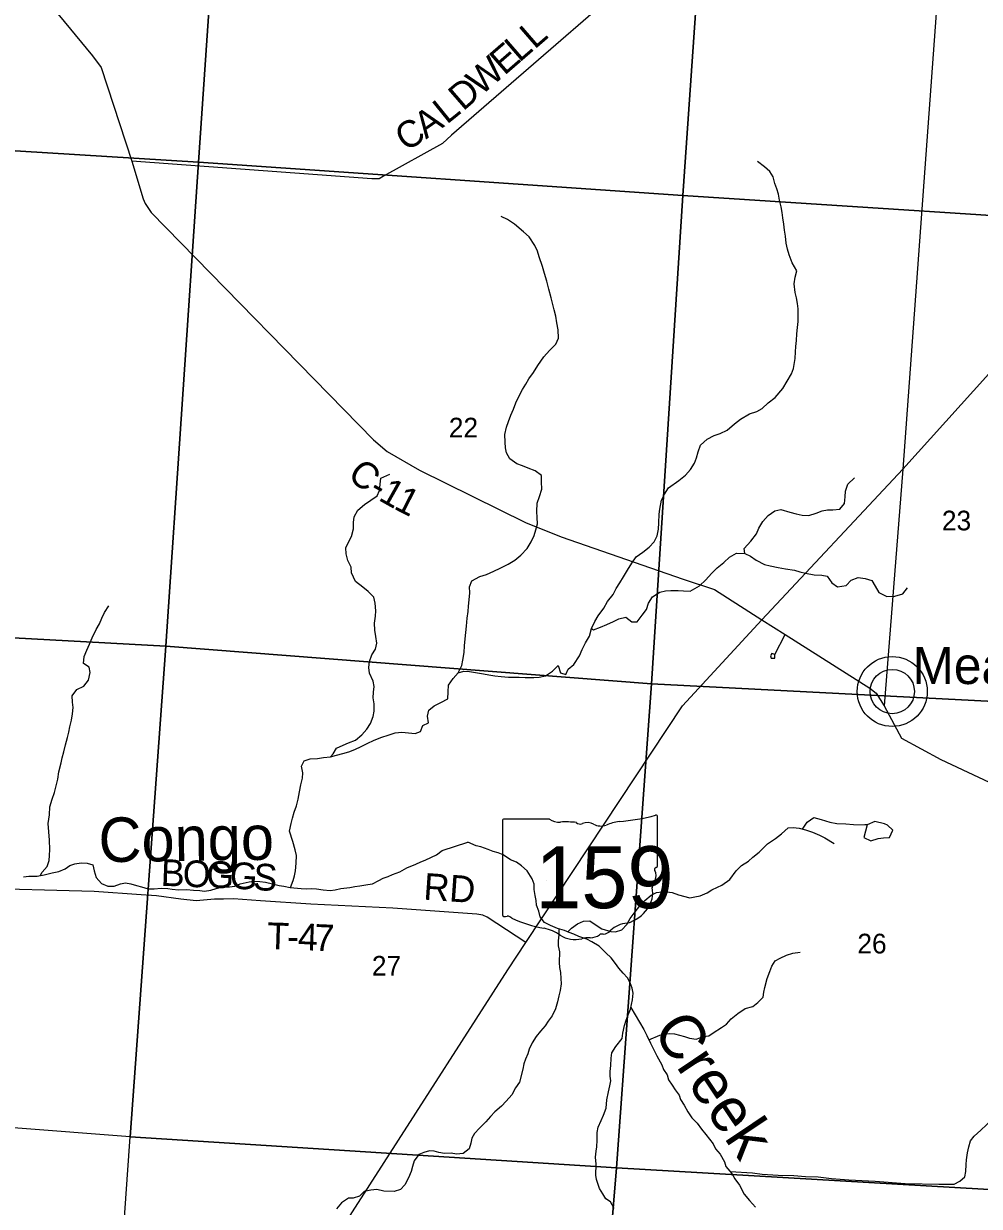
# Model space of a CAD drawing. Extents: x 1643459 to 2064572, y 425441 to 780708.
# Drawn here: x 1852387 to 1863118, y 542483 to 555768 of the extents above; entities that cross this region are included whole.
import ezdxf

# ---------------------------------------------------------------- set-up
doc = ezdxf.new("R2010")
doc.units = 0
for name, color, linetype in [('GE_P_Alignment_100_Curve_Data', 7, 'Continuous'), ('GM_X_Adjacent_County', 7, 'Continuous'), ('GM_X_County', 7, 'Continuous'), ('GM_X_Interchange_Ramps', 7, 'Continuous'), ('GM_X_Major_River', 7, 'Continuous'), ('GM_X_Major_River_Text', 7, 'Continuous'), ('GM_X_Minor_Lake', 7, 'Continuous'), ('GM_X_Rail_Line', 7, 'Continuous'), ('GM_X_Section_Text', 7, 'Continuous'), ('GM_X_State_Route', 7, 'Continuous'), ('GM_X_Township_ROW', 7, 'Continuous'), ('GM_X_Township_Subdivision_Text', 7, 'Continuous'), ('GM_X_US_Route', 7, 'Continuous'), ('PM_P_Cells', 7, 'Continuous'), ('RD_X_Text', 7, 'Continuous'), ('ST_Details', 7, 'Continuous')]:
    doc.layers.add(name, color=color, linetype=linetype)

msp = doc.modelspace()

# ---------------------------------------------------------------- linework, layer by layer
at = {"layer": 'GE_P_Alignment_100_Curve_Data'}
for radius in [393, 249]:
    msp.add_circle((1862140, 548266), radius, dxfattribs=at)
at = {"layer": 'GM_X_County'}
msp.add_lwpolyline([(1860822, 548681), (1860786, 548692), (1860773, 548668), (1860782, 548642), (1860820, 548640), (1860823, 548681), (1860938, 548905)], dxfattribs=at)
at = {"layer": 'GM_X_Major_River_Text'}
for points in [[(1862916, 559716), (1862715, 557017), (1862259, 550763)], [(1859898, 556864), (1859897, 556864), (1857192, 554514), (1857090, 554421), (1856429, 554054), (1856379, 554026), (1856295, 554025), (1853603, 554223)], [(1862259, 550763), (1862259, 550763), (1862050, 548106)], [(1858025, 545447), (1857592, 545730), (1857542, 545752), (1857477, 545766), (1856531, 545831), (1855610, 545879), (1855048, 545914), (1854745, 545936), (1854631, 545934), (1854529, 545933), (1854326, 545916), (1854152, 545935), (1853877, 545972), (1853705, 545981), (1853179, 546018), (1851781, 546057), (1851715, 546069), (1851683, 546093), (1851646, 546127), (1851410, 546135), (1848838, 546297)]]:
    msp.add_lwpolyline(points, dxfattribs=at)
at = {"layer": 'GM_X_Minor_Lake'}
for points in [[(1846452, 560096), (1849195, 559926), (1849444, 559910), (1853159, 555407), (1853258, 555276), (1853603, 554223), (1853728, 553801), (1853750, 553748), (1853819, 553648), (1856316, 551094), (1856467, 550961), (1856830, 550751), (1858023, 550164), (1858422, 550003), (1859792, 549529), (1860143, 549412), (1860677, 549070)], [(1860677, 549070), (1860677, 549070), (1860938, 548905), (1861887, 548303), (1861961, 548249), (1862050, 548106), (1862245, 547741), (1862687, 547503), (1864681, 546568), (1865987, 545911), (1866232, 545790), (1866317, 545732), (1866543, 545497)]]:
    msp.add_lwpolyline(points, dxfattribs=at)
at = {"layer": 'GM_X_Rail_Line'}
msp.add_line((1862140, 548266), (1862140, 548266), dxfattribs=at)
at = {"layer": 'GM_X_State_Route'}
for points in [[(1849223, 559965), (1854721, 559628), (1854349, 554212), (1848897, 554550)], [(1854721, 559628), (1860164, 559226), (1859790, 553839), (1854349, 554212)], [(1860164, 559226), (1865614, 558892), (1865211, 553484), (1859790, 553839)], [(1848897, 554550), (1854349, 554212), (1853983, 548777), (1848566, 549071)], [(1854349, 554212), (1859790, 553839), (1859437, 548353), (1853983, 548777)], [(1859790, 553839), (1865211, 553484), (1864802, 548077), (1859437, 548353)], [(1853983, 548777), (1853583, 543265), (1848193, 543679), (1848566, 549071)], [(1859437, 548353), (1859042, 542917), (1853583, 543265), (1853983, 548777)], [(1859437, 548353), (1864802, 548077), (1864390, 542605), (1859042, 542917)], [(1853583, 543265), (1859042, 542917), (1858602, 537565), (1858480, 537574), (1853210, 537937)], [(1859042, 542917), (1864390, 542605), (1863986, 537192), (1858602, 537565)]]:
    msp.add_lwpolyline(points, close=True, dxfattribs=at)
at = {"layer": 'GM_X_Township_Subdivision_Text'}
for points in [[(1861860, 546769), (1861819, 546627), (1861901, 546590), (1861983, 546614), (1862041, 546624), (1862109, 546627), (1862146, 546707), (1862086, 546766), (1862053, 546779)], [(1862053, 546779), (1861944, 546805), (1861860, 546769)]]:
    msp.add_lwpolyline(points, dxfattribs=at)
at = {"layer": 'GM_X_US_Route'}
for points in [[(1857267, 548475), (1857331, 548496), (1857393, 548490), (1857483, 548477), (1857549, 548465), (1857609, 548454), (1857677, 548442), (1857749, 548435), (1857831, 548429), (1857891, 548428), (1857951, 548426), (1858019, 548422), (1858115, 548423), (1858175, 548427), (1858245, 548442), (1858325, 548496), (1858390, 548558), (1858415, 548477), (1858475, 548457), (1858501, 548517), (1858564, 548569), (1858630, 548668), (1858657, 548739), (1858697, 548813), (1858740, 548889), (1858764, 548973), (1858799, 549053), (1858837, 549117), (1858900, 549203), (1858944, 549277), (1859005, 549354), (1859041, 549424), (1859081, 549488), (1859122, 549556), (1859168, 549630), (1859217, 549708), (1859263, 549778), (1859340, 549832), (1859412, 549888), (1859466, 549948), (1859499, 550016), (1859515, 550090), (1859520, 550162), (1859522, 550258), (1859531, 550316), (1859549, 550417), (1859584, 550483), (1859626, 550553), (1859743, 550636), (1859817, 550698), (1859876, 550760), (1859918, 550832), (1859942, 550892), (1859961, 550960), (1859985, 551034), (1860062, 551100), (1860142, 551143), (1860208, 551165), (1860286, 551203), (1860367, 551274), (1860437, 551326), (1860538, 551384), (1860618, 551413), (1860680, 551445), (1860748, 551507), (1860825, 551568), (1860912, 551670), (1861009, 551834), (1861031, 551896), (1861048, 552005), (1861054, 552083), (1861058, 552141), (1861063, 552209), (1861069, 552283), (1861076, 552356), (1861082, 552424), (1861085, 552496), (1861083, 552566), (1861075, 552624), (1861066, 552689), (1861050, 552749), (1861037, 552844), (1861051, 552920), (1861070, 552990), (1861016, 553082), (1860981, 553173), (1860963, 553235), (1860949, 553302), (1860942, 553382), (1860930, 553450), (1860921, 553515), (1860911, 553585), (1860902, 553645), (1860892, 553709), (1860874, 553786), (1860863, 553852), (1860843, 553912), (1860823, 553971), (1860804, 554047), (1860766, 554108), (1860705, 554160)], [(1860705, 554160), (1860625, 554219)], [(1858375, 552409), (1858361, 552481), (1858342, 552554), (1858330, 552612), (1858311, 552688), (1858285, 552787), (1858260, 552875), (1858236, 552960), (1858213, 553042), (1858175, 553149), (1858156, 553211), (1858126, 553276), (1858063, 553372), (1857999, 553431), (1857899, 553514), (1857818, 553569), (1857748, 553601)], [(1855409, 546581), (1855371, 546697), (1855389, 546783), (1855404, 546845), (1855424, 546909), (1855451, 546983), (1855469, 547055), (1855486, 547139), (1855500, 547216), (1855519, 547292), (1855523, 547354), (1855507, 547426), (1855536, 547488), (1855604, 547508), (1855686, 547515), (1855754, 547525), (1855832, 547532), (1855898, 547552), (1855972, 547568), (1856037, 547589), (1856105, 547613), (1856177, 547649), (1856243, 547682), (1856324, 547720), (1856410, 547752), (1856480, 547775), (1856558, 547803), (1856634, 547808), (1856710, 547800), (1856782, 547793), (1856842, 547817), (1856869, 547883), (1856933, 547915), (1856923, 547989), (1856936, 548057), (1856998, 548107), (1857070, 548141), (1857149, 548184), (1857153, 548263), (1857158, 548339), (1857210, 548411), (1857267, 548475), (1857307, 548559), (1857319, 548619), (1857332, 548705), (1857338, 548779), (1857345, 548857), (1857353, 548928), (1857360, 549000), (1857368, 549090), (1857377, 549166), (1857381, 549226), (1857388, 549297), (1857396, 549375), (1857392, 549443), (1857421, 549511), (1857509, 549557), (1857583, 549580), (1857668, 549616), (1857736, 549650), (1857826, 549697), (1857901, 549743), (1857969, 549797), (1858039, 549872), (1858086, 549948), (1858120, 550020), (1858139, 550081), (1858157, 550149), (1858154, 550219), (1858150, 550287), (1858153, 550381), (1858179, 550458), (1858204, 550540), (1858202, 550622), (1858202, 550692), (1858129, 550745), (1858053, 550775), (1857989, 550800), (1857923, 550824), (1857847, 550879), (1857810, 550946), (1857798, 551004), (1857793, 551068), (1857789, 551152), (1857808, 551237), (1857830, 551299), (1857858, 551371), (1857887, 551437), (1857915, 551509), (1857950, 551589), (1857990, 551657), (1858025, 551717), (1858061, 551779), (1858113, 551851), (1858160, 551929), (1858227, 552027), (1858293, 552096), (1858363, 552166), (1858392, 552234), (1858390, 552329), (1858375, 552409)], [(1855832, 547532), (1855864, 547566), (1855899, 547630), (1855973, 547664), (1856035, 547690), (1856113, 547721), (1856186, 547779), (1856240, 547843), (1856281, 547907), (1856313, 547987), (1856324, 548047), (1856322, 548129), (1856312, 548196), (1856317, 548260), (1856323, 548324), (1856312, 548382), (1856272, 548473), (1856262, 548537), (1856271, 548605), (1856297, 548677), (1856338, 548741), (1856354, 548810), (1856341, 548884), (1856329, 548954), (1856326, 549033), (1856338, 549113), (1856340, 549173), (1856335, 549257), (1856319, 549324), (1856256, 549390), (1856194, 549439), (1856114, 549501), (1856069, 549598), (1856063, 549664), (1856026, 549739), (1856008, 549811), (1856005, 549879), (1856033, 549942), (1856067, 550008), (1856092, 550092), (1856090, 550166), (1856099, 550230), (1856141, 550304), (1856214, 550368), (1856286, 550416), (1856358, 550465), (1856383, 550525), (1856399, 550662), (1856500, 550709)], [(1860486, 549817), (1860478, 549871), (1860553, 549953), (1860616, 550038), (1860642, 550099), (1860688, 550177), (1860747, 550242), (1860821, 550296), (1860889, 550312), (1860989, 550281), (1861061, 550262), (1861129, 550248), (1861205, 550243), (1861285, 550269), (1861353, 550295), (1861414, 550306), (1861474, 550306), (1861550, 550313), (1861604, 550377), (1861612, 550454), (1861615, 550518), (1861641, 550596), (1861716, 550668)], [(1858764, 548973), (1858786, 548958), (1858864, 548990), (1858935, 549018), (1859011, 549051), (1859069, 549081), (1859147, 549101), (1859217, 549048), (1859277, 549050), (1859331, 549122), (1859380, 549189), (1859404, 549260), (1859449, 549330), (1859531, 549381), (1859593, 549397), (1859653, 549402), (1859735, 549400), (1859797, 549398), (1859871, 549393), (1859974, 549453), (1860046, 549522), (1860109, 549590), (1860173, 549654), (1860247, 549714), (1860312, 549774), (1860392, 549819), (1860486, 549817), (1860550, 549786), (1860612, 549740), (1860705, 549693), (1860769, 549676), (1860857, 549660), (1860941, 549645), (1861041, 549628), (1861103, 549612), (1861167, 549595), (1861263, 549577), (1861349, 549572), (1861409, 549560), (1861461, 549487), (1861526, 549441), (1861622, 549456), (1861677, 549516), (1861757, 549545), (1861835, 549537), (1861909, 549514), (1861949, 549450), (1861990, 549377), (1862078, 549333), (1862170, 549338), (1862258, 549364), (1862311, 549430)], [(1852678, 546595), (1852662, 546784), (1852678, 546880), (1852681, 546971), (1852706, 547055), (1852734, 547133), (1852753, 547205), (1852771, 547283), (1852784, 547363), (1852808, 547464), (1852821, 547522), (1852837, 547588), (1852858, 547666), (1852880, 547750), (1852893, 547808), (1852907, 547870), (1852925, 547945), (1852936, 548015), (1852942, 548085), (1852935, 548145), (1852931, 548219), (1852984, 548287), (1853062, 548327), (1853114, 548395), (1853135, 548481), (1853123, 548541), (1853061, 548580), (1853068, 548658), (1853098, 548732), (1853127, 548798), (1853155, 548868), (1853202, 548962), (1853238, 549026), (1853265, 549090), (1853295, 549154), (1853343, 549230)], [(1861133, 546719), (1861186, 546798), (1861260, 546849), (1861342, 546827), (1861438, 546798), (1861518, 546785), (1861620, 546779), (1861704, 546774), (1861860, 546769), (1861831, 546769)], [(1860740, 546555), (1860829, 546615), (1860895, 546669), (1860970, 546735), (1861028, 546740), (1861096, 546732), (1861164, 546711), (1861245, 546685), (1861323, 546652), (1861383, 546624), (1861489, 546559)], [(1852385, 546186), (1852446, 546191), (1852540, 546190), (1852618, 546207), (1852707, 546228), (1852781, 546245), (1852854, 546276), (1852904, 546312), (1852963, 546331), (1853033, 546341), (1853101, 546338), (1853163, 546319), (1853180, 546252), (1853203, 546176), (1853263, 546109), (1853331, 546080), (1853403, 546079), (1853475, 546106), (1853532, 546117), (1853590, 546105), (1853654, 546086), (1853710, 546073), (1853784, 546050), (1853854, 546049), (1853932, 546058), (1854006, 546053), (1854056, 546045), (1854126, 546038), (1854217, 546041), (1854293, 546034), (1854367, 546029), (1854417, 546022), (1854487, 546033), (1854550, 546055), (1854624, 546072), (1854698, 546073), (1854759, 546080), (1854817, 546105), (1854920, 546130), (1854970, 546136), (1855038, 546133), (1855104, 546124), (1855180, 546105), (1855256, 546088), (1855310, 546081), (1855380, 546064), (1855502, 546053), (1855566, 546048), (1855623, 546053), (1855675, 546051), (1855749, 546040), (1855829, 546031), (1855885, 546038), (1855950, 546053), (1856048, 546064), (1856104, 546075), (1856162, 546085), (1856253, 546098), (1856305, 546107), (1856374, 546144), (1856424, 546170), (1856479, 546189), (1856529, 546209), (1856610, 546242), (1856690, 546287), (1856791, 546328), (1856846, 546351), (1856896, 546373), (1856967, 546404), (1857021, 546432), (1857086, 546479), (1857375, 546572)], [(1852572, 546197), (1852596, 546237), (1852651, 546301), (1852674, 546367), (1852679, 546423), (1852680, 546492), (1852678, 546595)], [(1855383, 546064), (1855415, 546144), (1855428, 546194), (1855438, 546250), (1855448, 546339), (1855449, 546425), (1855437, 546489), (1855409, 546581)], [(1859037, 544277), (1859108, 544367), (1859113, 544429), (1859134, 544515), (1859151, 544573), (1859173, 544633), (1859200, 544697), (1859222, 544803), (1859231, 544877), (1859221, 544932), (1859196, 544992), (1859168, 545049), (1859119, 545102), (1859071, 545157), (1859034, 545211), (1858985, 545274), (1858923, 545331), (1858850, 545404), (1858768, 545454), (1858710, 545485), (1858620, 545514), (1858565, 545539), (1858513, 545559), (1858459, 545580), (1858383, 545605), (1858303, 545638), (1858237, 545673), (1858188, 545734), (1858171, 545797), (1858147, 545865), (1858142, 545920), (1858131, 545976), (1858121, 546042), (1858118, 546101), (1858097, 546163), (1858040, 546252), (1857976, 546309), (1857922, 546350), (1857853, 546375), (1857771, 546430), (1857715, 546453), (1857659, 546470), (1857601, 546493), (1857521, 546522), (1857469, 546531), (1857375, 546572)], [(1858497, 545565), (1858537, 545609), (1858604, 545657), (1858675, 545688), (1858745, 545691), (1858817, 545642), (1858880, 545599), (1858980, 545570), (1859032, 545565), (1859103, 545590), (1859160, 545648), (1859196, 545716), (1859254, 545793), (1859304, 545857), (1859363, 545918), (1859432, 545980), (1859491, 546007), (1859557, 546014), (1859609, 546016), (1859667, 546007), (1859741, 545982), (1859867, 545950), (1859925, 545958), (1859982, 545971), (1860062, 546006), (1860113, 546038), (1860177, 546067), (1860228, 546089), (1860315, 546154), (1860386, 546251), (1860449, 546311), (1860524, 546360), (1860576, 546404), (1860645, 546461), (1860740, 546555)], [(1858392, 545602), (1858397, 545605), (1858396, 545533), (1858387, 545464), (1858389, 545410), (1858402, 545342), (1858400, 545221), (1858404, 545165), (1858415, 545109), (1858420, 545042), (1858422, 544982), (1858411, 544908), (1858398, 544846), (1858381, 544782), (1858358, 544701), (1858321, 544622), (1858278, 544562), (1858241, 544510), (1858191, 544450), (1858142, 544389), (1858095, 544321), (1858062, 544249), (1858047, 544195), (1858022, 544137), (1858002, 544083), (1857991, 544023), (1857953, 543879), (1857910, 543813), (1857867, 543737), (1857804, 543664), (1857753, 543610), (1857676, 543545), (1857630, 543493), (1857575, 543431), (1857504, 543360), (1857449, 543300), (1857420, 543249), (1857407, 543194), (1857389, 543130), (1857322, 543075), (1857246, 543070), (1857189, 543079), (1857113, 543078), (1857047, 543086), (1856995, 543101), (1856945, 543106), (1856879, 543089), (1856824, 543065), (1856771, 542995), (1856753, 542931), (1856740, 542875), (1856707, 542805), (1856668, 542723), (1856617, 542672), (1856547, 542651), (1856432, 542652), (1856352, 542671), (1856284, 542664), (1856210, 542651), (1856157, 542599), (1856086, 542574), (1856036, 542573), (1855957, 542521), (1855900, 542454)], [(1859408, 544353), (1859532, 544406), (1859584, 544421), (1859644, 544424), (1859694, 544420), (1859752, 544405), (1859806, 544390), (1859864, 544373), (1859938, 544362), (1860019, 544390), (1860079, 544399), (1860130, 544432), (1860221, 544491), (1860279, 544529), (1860332, 544591), (1860405, 544650), (1860490, 544705), (1860576, 544728), (1860629, 544774), (1860692, 544833), (1860697, 544889), (1860709, 544943), (1860737, 545042), (1860764, 545120), (1860786, 545182), (1860825, 545239), (1860882, 545271), (1860952, 545306), (1861023, 545325), (1861107, 545338)], [(1859204, 544716), (1859350, 544468), (1859383, 544403), (1859426, 544315), (1859450, 544262), (1859497, 544173), (1859554, 544072), (1859571, 544021), (1859611, 543959), (1859628, 543904), (1859669, 543843), (1859703, 543793), (1859746, 543732), (1859762, 543682), (1859805, 543619), (1859846, 543544), (1859888, 543477), (1859951, 543416), (1859998, 543351), (1860046, 543290), (1860129, 543185), (1860156, 543128), (1860206, 543069), (1860255, 542984), (1860272, 542932), (1860339, 542851), (1860371, 542792), (1860424, 542721), (1860477, 542618), (1860536, 542549), (1860606, 542472)], [(1859017, 542457), (1858976, 542532), (1858924, 542569), (1858889, 542622), (1858851, 542682), (1858818, 542783), (1858813, 542833), (1858814, 542956), (1858809, 543036), (1858814, 543101), (1858823, 543151), (1858826, 543225), (1858827, 543311), (1858836, 543372), (1858873, 543447), (1858897, 543507), (1858926, 543587), (1858937, 543678), (1858955, 543768), (1858967, 543838), (1858980, 543892), (1858971, 543946), (1858973, 543999), (1858980, 544065), (1858985, 544149), (1858992, 544209), (1859037, 544277)], [(1862663, 542731), (1862835, 542731), (1862899, 542767), (1862955, 542814), (1862965, 542875), (1862971, 542953), (1862975, 543007), (1862984, 543085), (1862998, 543151), (1863018, 543217), (1863060, 543273), (1863134, 543337), (1863197, 543399), (1863263, 543466), (1863319, 543512)], [(1860319, 542876), (1860571, 542858), (1860678, 542846), (1860860, 542834), (1861034, 542830), (1861165, 542819)], [(1861165, 542819), (1861308, 542814), (1861458, 542794), (1861652, 542782), (1861949, 542767), (1862286, 542739), (1862671, 542731)]]:
    msp.add_lwpolyline(points, dxfattribs=at)
at = {"layer": 'RD_X_Text'}
msp.add_lwpolyline([(1853658, 538647), (1857824, 545139), (1858025, 545447), (1859784, 548105), (1860677, 549070), (1862259, 550763), (1863223, 551835), (1863365, 551991), (1867522, 555003), (1870936, 557440), (1872282, 558358), (1876521, 561111), (1878743, 562632), (1878993, 562781), (1879491, 563044), (1881881, 563743), (1885154, 564722), (1885648, 564775), (1886516, 564866), (1886708, 564902), (1886850, 564973), (1887258, 565264), (1887306, 565299)], dxfattribs=at)
at = {"layer": 'ST_Details'}
for p, q in [((1858291, 546833), (1857781, 546833)), ((1859504, 546306), (1859504, 546859)), ((1857764, 546815), (1857764, 545758)), ((1859504, 546306), (1859504, 546306))]:
    msp.add_line(p, q, dxfattribs=at)
for centre, major_axis, start_param, end_param in [((1857784, 546817), (20.2, 0), 1.712693, 3.28349), ((1858412, 546955), (196, 0), 4.042523, 4.731795), ((1858884, 548273), (1845, 0), 4.814394, 5.042369), ((1859485, 546861), (19.4, 0), 6.141152, 7.989035), ((1858477, 546240), (702, 0), 1.404758, 1.657858), ((1858636, 546822), (56.4, 0), 3.836095, 5.185415), ((1858719, 546700), (117, 0), 0.950623, 2.079405), ((1858870, 546868), (141, 0), 4.081561, 5.145723), ((1859120, 546510), (371, 0), 1.699011, 2.107814), ((1859500, 546266), (30, 0), 1.883978, 3.671073), ((1859483, 546304), (20.7, 0), 5.05454, 6.418171), ((1859309, 546196), (180, 0), 5.934695, 6.695948), ((1858988, 546005), (462, 0), 5.101752, 6.440018), ((1859573, 546075), (131, 0), 2.387724, 3.262537), ((1857784, 545756), (20.3, 0), 3.00124, 4.508301), ((1857787, 545864), (155, 0), 4.665946, 4.897461), ((1857819, 545697), (56, 0), 0.519207, 1.627899), ((1858525, 546646), (1333, 0), 4.195997, 4.488961), ((1859182, 545461), (253, 0), 1.647645, 2.488434), ((1858128, 545283), (417, 0), 0.823519, 1.323587), ((1858579, 545692), (265, 0), 4.026481, 4.996735), ((1858732, 545326), (217, 0), 1.495662, 1.94098), ((1858751, 545613), (141, 0), 4.691044, 5.507374), ((1858879, 545510), (39.7, 0), 1.147584, 2.315152), ((1858862, 545655), (149, 0), 4.937069, 5.64225)]:
    msp.add_ellipse(centre, major_axis=major_axis, ratio=0.8, start_param=start_param, end_param=end_param, dxfattribs=at)

# ---------------------------------------------------------------- texts
at = {"layer": 'GM_X_Adjacent_County'}
for s, p in [('22', (1857161, 551120)), ('23', (1862697, 550076)), ('26', (1861748, 545324)), ('27', (1856297, 545075))]:
    msp.add_text(s, height=221, rotation=0, dxfattribs=at).set_placement(p)
at = {"layer": 'GM_X_Interchange_Ramps'}
for s, rotation, p in [('Congo', 0.8568, (1853231, 546348)), ('Creek', 303.8556, (1859438, 544458))]:
    msp.add_text(s, height=500, rotation=rotation, dxfattribs=at).set_placement(p)
at = {"layer": 'GM_X_Major_River'}
for s, rotation, p in [('L', 40.9217, (1858123, 555473)), ('L', 40.9217, (1857953, 555326)), ('E', 40.9217, (1857784, 555179)), ('W', 40.9217, (1857521, 554951)), ('D', 40.9217, (1857321, 554779)), ('A', 35.0445, (1856904, 554465)), ('L', 38.9626, (1857138, 554630)), ('C', 31.1263, (1856675, 554326)), ('B', 357.8666, (1853923, 546084)), ('O', 357.8667, (1854169, 546074)), ('G', 357.6424, (1854433, 546065)), ('G', 356.8474, (1854695, 546054)), ('S', 356.3342, (1854958, 546039)), ('RD', 356.0551, (1856870, 545929)), ('T', 358.2975, (1855117, 545373)), ('4', 357.7684, (1855462, 545363)), ('7', 357.4115, (1855645, 545355)), ('-', 358.0504, (1855341, 545367))]:
    msp.add_text(s, height=300, rotation=rotation, dxfattribs=at).set_placement(p)
at = {"layer": 'GM_X_Section_Text'}
for s, rotation, p in [('C', 319.3814, (1856010, 550679)), ('-', 331.0133, (1856251, 550481)), ('1', 330.6853, (1856359, 550422)), ('1', 332.8348, (1856531, 550325))]:
    msp.add_text(s, height=300, rotation=rotation, dxfattribs=at).set_placement(p)
at = {"layer": 'GM_X_Township_ROW'}
msp.add_text('Meade', height=417, rotation=0, dxfattribs=at).set_placement((1862367, 548350))
at = {"layer": 'PM_P_Cells'}
for s in ['s', 'r']:
    msp.add_text(s, height=1, dxfattribs=at).set_placement((1858614, 546216))
msp.add_text('159', height=1, rotation=0, dxfattribs=at).set_placement((1858261, 546143))
at = {"layer": 'ST_Details'}
msp.add_text('159', height=696.1, dxfattribs=at).set_placement((1858131, 545832))

doc.saveas('drawing.dxf')
